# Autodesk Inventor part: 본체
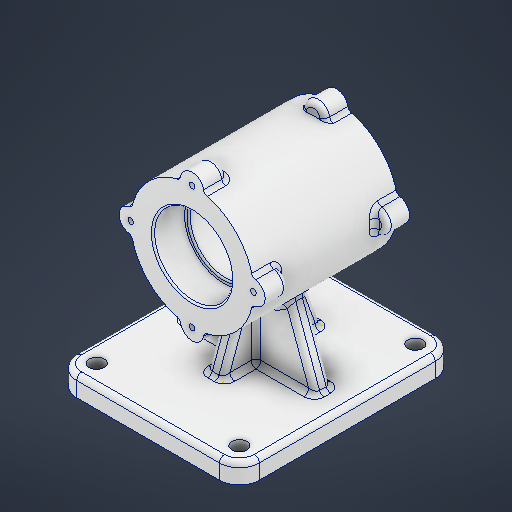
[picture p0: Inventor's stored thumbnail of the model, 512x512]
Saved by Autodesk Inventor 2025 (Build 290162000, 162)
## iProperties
Created: 2025-08
Part Number: 본체
Material: 알루미늄 6061
Document SubType Name: Modeling
Designer: infra012
Density: 2.7 g/cm^3
Appearance: 알루미늄 - 평지
Mass: 1222.05 g
Surface Area: 800.757 cm^2
Volume: 452.61 cm^3
Author: infra012
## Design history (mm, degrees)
sketch "스케치1"
  geometry: 1 further point
sketch "스케치2"
  geometry: L1 (-55, -65)-(55, -65); L2 (55, -65)-(55, 65); L3 (55, 65)-(-55, 65); L4 (-55, 65)-(-55, -65); L5 (-55, -65)-(55, 65); L6 (55, -65)-(-55, 65); 1 further point
  constraints: 12 end point, 2 midpoint, 2 parallel, 1 horizontal, 1 perpendicular
  dimensions: "d0" = 110 distance of L3.end L2.end; "d1" = 130 distance of L2.end L1.end
extrude "돌출1" new body sketch "스케치2" distance "d2" = 12; taper "d3" = 0 deg
sketch "스케치3"
  geometry: 1 further point
sketch "스케치4"
  geometry: L1 (119, 38.5)-(82, 38.5); L2 (82, 38.5)-(82, -48.5); L3 (82, -48.5)-(119, -48.5); L4 (119, -48.5)-(119, 38.5); L5 (82, 38.5)-(105.5, 38.5); L6 (105.5, 38.5)-(105.5, 19.5); L7 (105.5, 19.5)-(82, 19.5); L8 (82, 19.5)-(82, 38.5); L9 (82, -48.5)-(105.5, -48.5); L10 (105.5, -48.5)-(105.5, -29.5); L11 (105.5, -29.5)-(82, -29.5); L12 (82, -29.5)-(82, -48.5); L13 (82, 19.5)-(103, 19.5); L14 (103, 19.5)-(103, -29.5); L15 (103, -29.5)-(82, -29.5); L16 (82, -29.5)-(82, 19.5); L17 (0, 65)-(12, 65) reference; L18 (0, 65)-(0, -65) reference; 6 further points
  constraints: 32 end point, 8 parallel, 4 horizontal, 4 perpendicular, 2 midpoint, 1 point on line
  dimensions: "d4" = 37 distance of L3.end L2.end; "d5" = 87 distance of L2.end L1.end; "d6" = 23.5 distance of L6.end L7.end; "d7" = 19 distance of L5.end L6.end; "d8" = 23.5 distance of L11.end L10.end; "d9" = 19 distance of L10.end L9.end; "d10" = 21 distance of L14.end L15.end; "d11" = 70 distance from line of point (82, -5) L17; "d12" = 82 distance from line of L18 point (82, -5)
revolve "회전1" sketch "스케치4" stored, may be unused: angle "d13" = 90 deg
sketch "스케치5"
  geometry: C1 r 7 at (0, 37); C2 r 7 at (-37, 0); C3 r 7 at (-37, 0); C4 r 7 at (0, -37); C5 r 7 at (37, 0); A1 r 37 centre (0, 0) between (0, 37) and (-37, 0) reference; 9 further points
  constraints: 5 centre point, 2 point on circle, 9 other
  dimensions: "d14" = 14 diameter of C1; "d15" = 14 diameter of C2; "d18" = 360 deg dimension on A1.centre C1.centre (derived)
extrude "돌출2" join sketch "스케치5" distance "d20" = 14; taper "d21" = 0 deg
sketch "스케치6"
  geometry: C1 r 7 at (0, 37); C2 r 7 at (-37, 0); C3 r 7 at (0, -37); C4 r 7 at (37, 0); 10 further points
  constraints: 4 centre point, 11 other
  dimensions: "d22" = 14 diameter of C1; "d25" = 360 deg dimension on point (0, 0) C1.centre (derived)
extrude "돌출3" join sketch "스케치6" distance "d27" = 14; taper "d28" = 0 deg
sketch "스케치7"
  geometry: 1 further point
node "스케치8"
sketch "스케치11"
  geometry: 1 further point
sketch "스케치12"
  geometry: 1 further point
sketch "스케치13"
  geometry: L1 (12, 25)-(58.061, 8.235); L2 (12, -35)-(55.537, -19.154); 3 further points
  constraints: 4 end point, 2 vertical alignment
  dimensions: "d35" = 60 distance of L2.start L1.start; "d36" = 40 distance of point (12, 65) L1.start
sketch "스케치14"
  geometry: 1 further point
sketch "스케치15"
  geometry: 1 further point
sketch "스케치16"
  geometry: 1 further point
sketch "스케치17"
  geometry: L1 (5, 35)-(-5, 35); L2 (-5, 35)-(-5, -25); L3 (-5, -25)-(5, -25); L4 (5, -25)-(5, 35); L5 (5, 35)-(-5, -25); L6 (-5, 35)-(5, -25); L7 (-55, -65)-(55, -65) reference; L8 (43, 10)-(-43, 10); L9 (-43, 10)-(-43, 0); L10 (-43, 0)-(43, 0); L11 (43, 0)-(43, 10); L12 (43, 10)-(-43, 0); L13 (-43, 10)-(43, 0); L14 (5, 0)-(-5, 0); L15 (-5, 0)-(-5, 10); L16 (-5, 10)-(5, 10); L17 (5, 10)-(5, 0); L18 (5, 0)-(-5, 10); L19 (-5, 0)-(5, 10); 6 further points
  constraints: 36 end point, 6 midpoint, 6 parallel, 3 horizontal, 3 perpendicular
  dimensions: "d39" = 10 distance of L3.end L2.end; "d40" = 60 distance of L2.end L1.end; "d41" = 70 distance from line of L7 point (0, 5); "d42" = 86 distance of L10.end L9.end; "d43" = 10 distance of L9.end L8.end; "d44" = 10 distance of L15.end L16.end; "d45" = 10 distance of L14.end L15.end
sketch "스케치18"
  geometry: 1 further point
sketch "스케치19"
  geometry: 1 further point
sketch "스케치20"
  geometry: 1 further point
extrude "돌출5" join sketch "스케치17" stored distance "d46" = 10; taper "d47" = 0 deg
sketch "스케치21"
  geometry: 1 further point
feature "리브1" dims "d48" = 1, "d49" = 10, "d50" = 0, "d51" = 0, "d52" = 1, "d53" = 1
sketch "스케치22"
  geometry: L1 (12, -35)-(50.309, -21.057); L2 (12, 65)-(12, -65) reference; 2 further points
  constraints: 2 end point, 1 vertical alignment
  dimensions: "d54" = 110 deg angle of L2 L1; "d55" = 60 distance of point (12, 25) L1.start
feature "리브2" sketch "스케치22" dims "d56" = 1, "d57" = 10, "d58" = 0, "d59" = 0, "d60" = 1, "d61" = 1
sketch "스케치23"
  geometry: L1 (5, 35)-(5, -25) reference; 2 further points
  constraints: 1 midpoint
sketch "스케치24"
  geometry: L1 (41, 12)-(20.479, 68.382); L2 (55, 12)-(-55, 12) reference; 1 further point
  constraints: 2 end point
  dimensions: "d62" = 14 distance of L2.start L1.start; "d63" = 60 distance of L1.start L1.end; "d64" = 110 deg angle of L2 L1; "d65" = 13.1557 distance from line of L2.start L1
feature "리브3" sketch "스케치24" dims "d66" = 1, "d67" = 10, "d68" = 0, "d69" = 0, "d70" = 1, "d71" = 1
sketch "스케치25"
  geometry: L1 (-41, 12)-(-22.486, 62.868); L2 (-55, 12)-(55, 12) reference; 1 further point
  constraints: 2 end point, 1 horizontal alignment
  dimensions: "d72" = 14 distance of L2.start L1.start; "d73" = 110 deg angle of L2 L1
feature "리브4" sketch "스케치25" dims "d74" = 1, "d75" = 10, "d76" = 0, "d77" = 0, "d78" = 1, "d79" = 1
sketch "스케치26"
  geometry: A1 r 7 centre (0, 0) between (6.969, -0.662) and (-6.969, -0.662) reference; A2 r 7 centre (-37, -37) between (-36.338, -30.031) and (-36.338, -43.969) reference; A3 r 7 centre (0, -74) between (-6.969, -73.338) and (6.969, -73.338) reference; A4 r 7 centre (37, -37) between (36.338, -43.969) and (36.338, -30.031) reference; 5 further points
  constraints: 4 coincident
hole "구멍1" sketch "스케치26" at (0, 0), (-37, -37), (0, -74), (37, -37) diameter "d80" = 3.242; stored, may be unused: countersink angle "d84" = 90 deg, drill point angle "d86" = 118 deg; dims "d81" = 8, "d82" = 4, "d83" = 2, "d85" = 10
sketch "스케치27"
  geometry: C1 r 1.621 at (0, 74) reference; C2 r 1.621 at (-37, 37) reference; C3 r 1.621 at (0, 0) reference; C4 r 1.621 at (37, 37) reference; 5 further points
  constraints: 4 coincident
hole "구멍2" sketch "스케치27" at (0, 74), (-37, 37), (0, 0), (37, 37) diameter "d87" = 3.242; stored, may be unused: countersink angle "d91" = 90 deg, drill point angle "d93" = 118 deg; dims "d88" = 8, "d89" = 4, "d90" = 2, "d92" = 10
sketch "스케치28"
  geometry: L1 (-43, -53)-(43, -53); L2 (43, -53)-(43, 53); L3 (43, 53)-(-43, 53); L4 (-43, 53)-(-43, -53); L5 (-43, -53)-(43, 53); L6 (43, -53)-(-43, 53); 5 further points
  constraints: 12 end point, 4 coincident, 2 midpoint, 2 parallel, 1 horizontal, 1 perpendicular
  dimensions: "d94" = 86 distance of L3.end L2.end; "d95" = 106 distance of L2.end L1.end
hole "구멍3" sketch "스케치28" at (43, 53), (-43, 53), (-43, -53), (43, -53) diameter "d96" = 9; stored, may be unused: countersink angle "d100" = 90 deg, drill point angle "d102" = 118 deg; dims "d97" = 8, "d98" = 4, "d99" = 2, "d101" = 10
fillet "모깎기1" dims "d103" = 12
fillet "모깎기2" dims "d104" = 3
fillet "모깎기3" dims "d105" = 3
fillet "모깎기4" dims "d106" = 3
fillet "모깎기5" dims "d107" = 1
node "솔리드1"
node "스케치 - 원형 패턴1" dims "d18" = 360 deg (derived)
node "스케치 - 원형 패턴2" dims "d25" = 360 deg (derived)
feature "A9D066F2-1C7D-4E18-AEED-F7BC21143FA4" dims "d96" = 9, "d97" = 8, "d98" = 4, "d99" = 2, "d100" = 90 deg, "d101" = 10, "d102" = 118 deg
